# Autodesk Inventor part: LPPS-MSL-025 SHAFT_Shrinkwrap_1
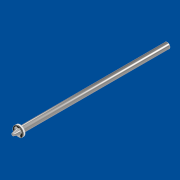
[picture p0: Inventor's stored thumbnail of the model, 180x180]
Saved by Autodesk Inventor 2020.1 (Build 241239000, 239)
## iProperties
Created: 2019-07
Part Number: LPPS-MSL-025 SHAFT_Shrinkwrap_1
Material: Generic
Document SubType Name: Modeling
Designer: J. Nielson
Density: 1 g/cm^3
Appearance: Default
Author: J. Nielson
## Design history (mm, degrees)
node "Assembly1" dims "d0" = 10
body "Solid1"
node "Part1:1" dims "d0" = 10
node "Part2:1" dims "d0" = 10
body "Solid2"
node "Part3:1" dims "d0" = 10
body "Solid3"
